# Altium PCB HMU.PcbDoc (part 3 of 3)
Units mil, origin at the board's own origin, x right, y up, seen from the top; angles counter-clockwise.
Board outline 6247.81 x 4035.43 mil, 4 copper layers (Top Layer, Mid-Layer 1, Mid-Layer 2, Bottom Layer), stack 90 mil thick; 310 components, 201 nets, 779 pads, 176 vias.
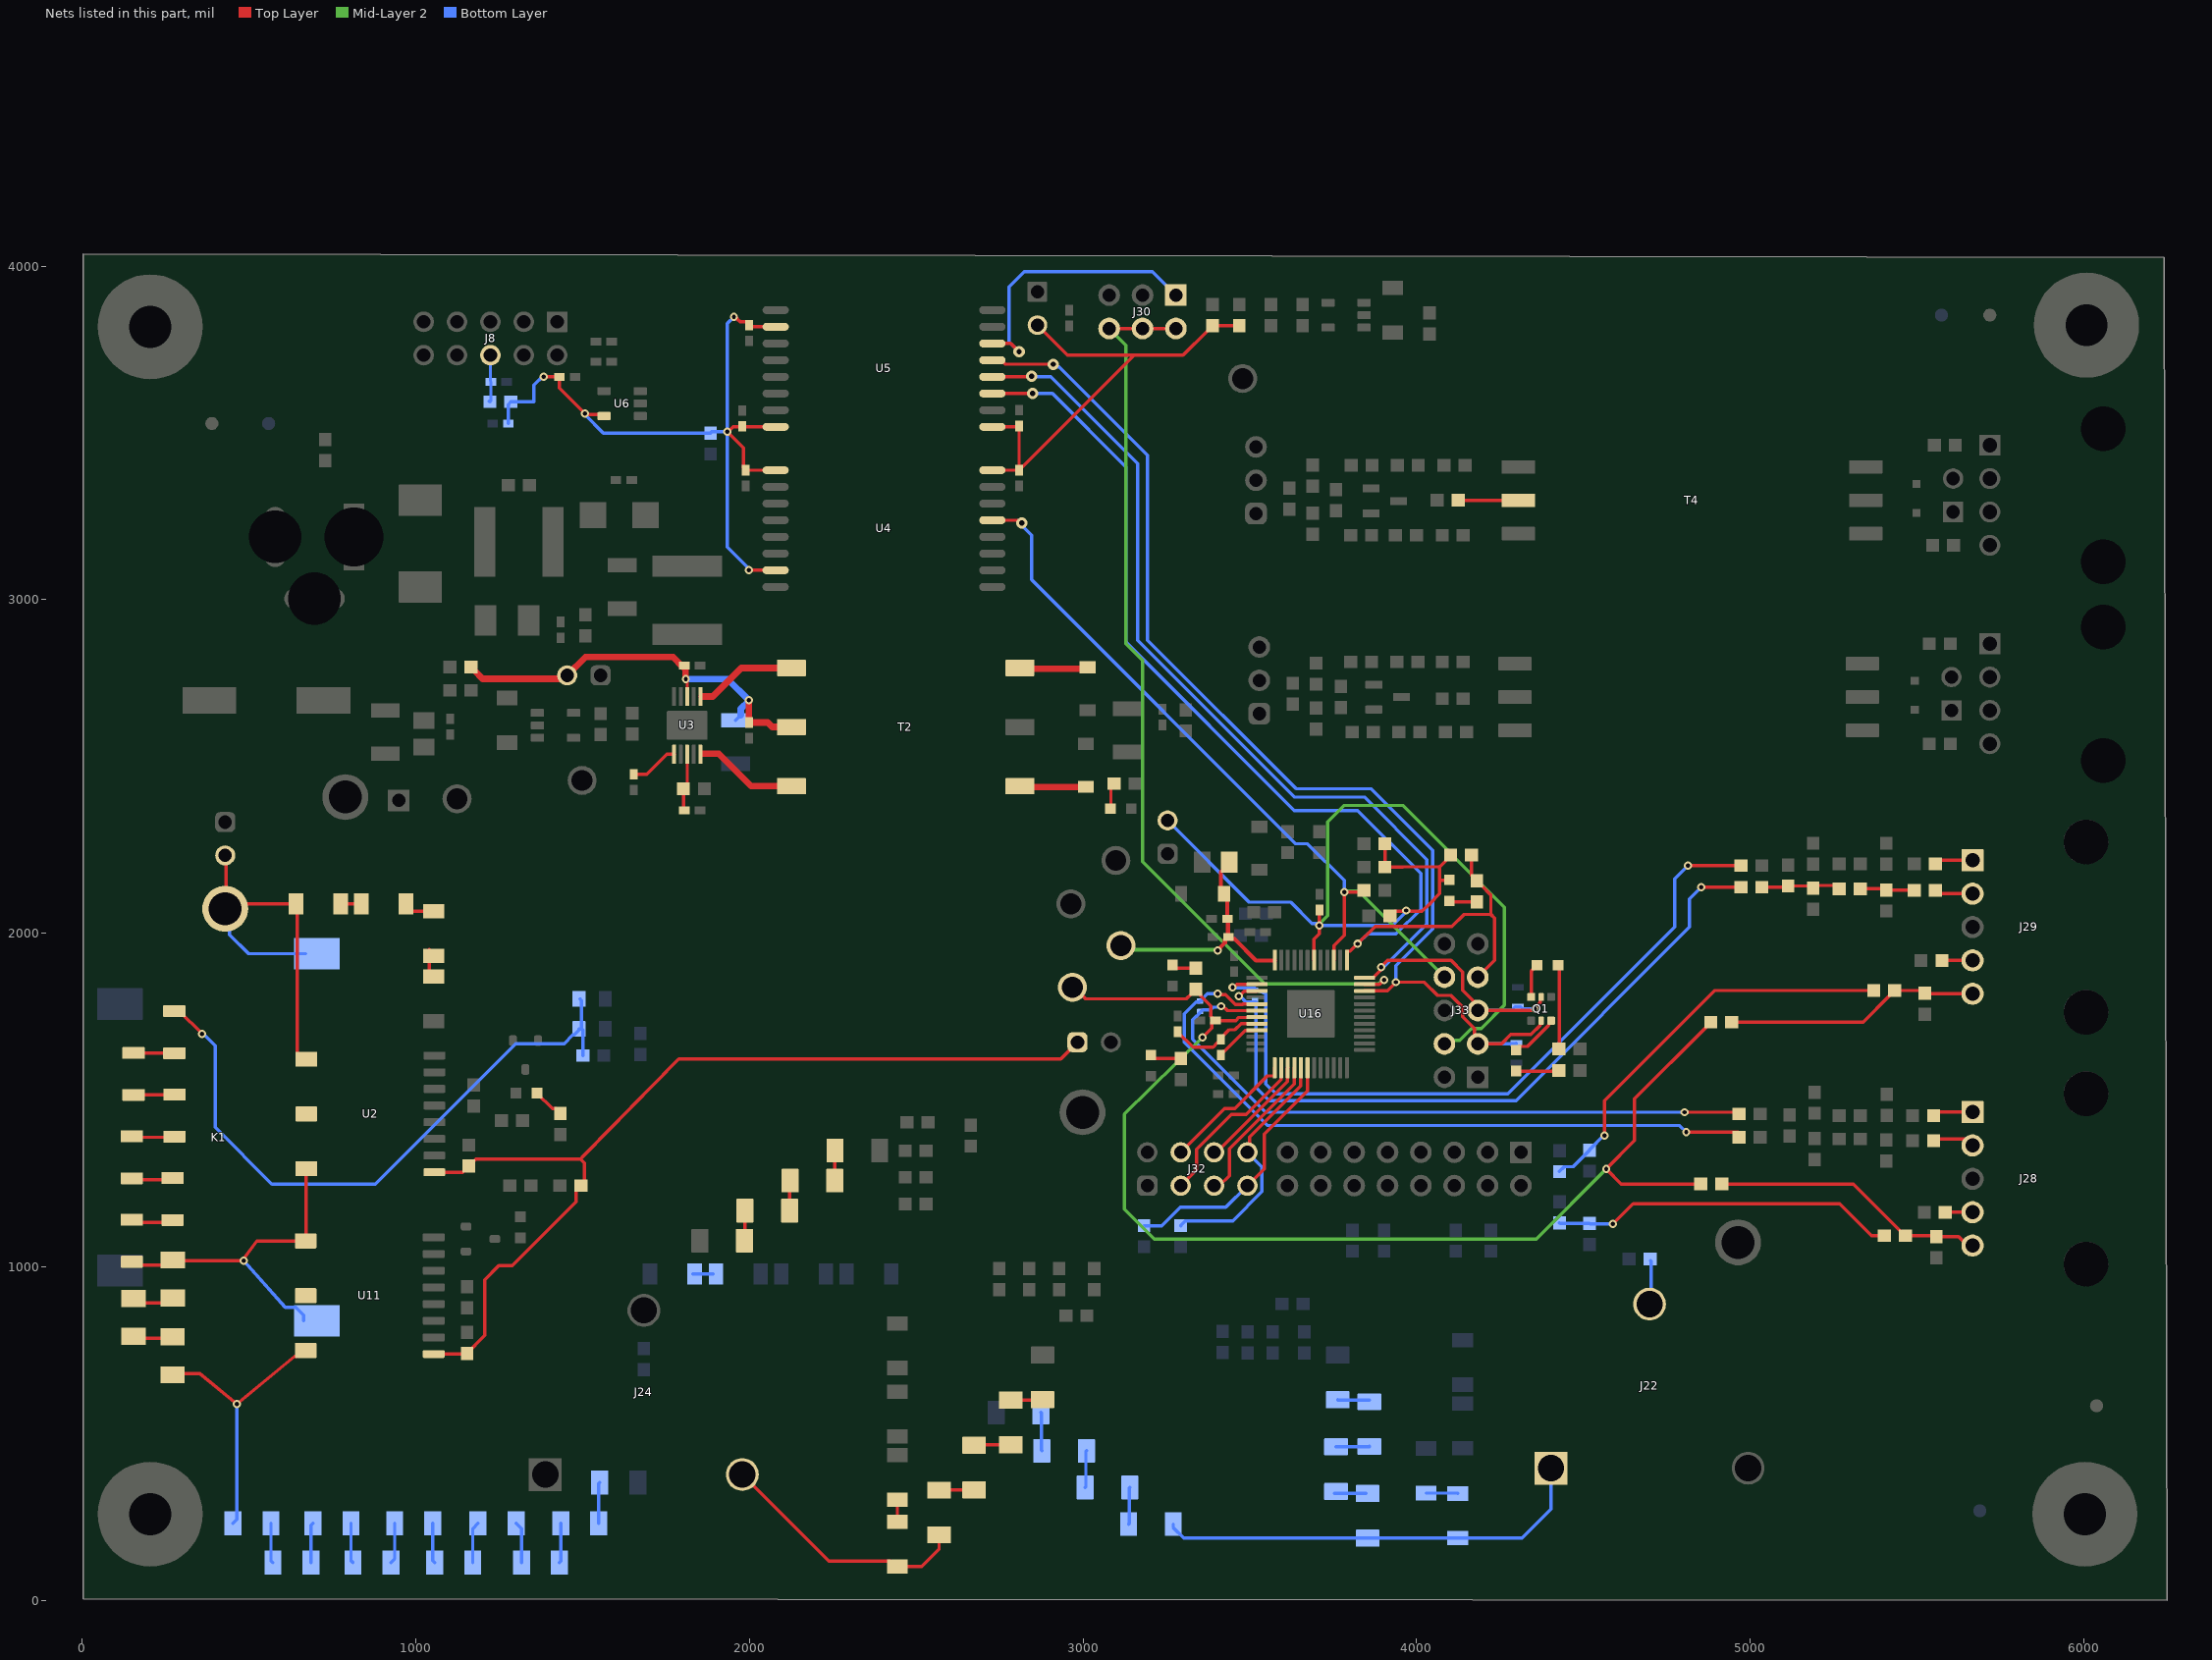
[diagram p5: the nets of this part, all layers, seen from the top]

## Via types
v1: diameter 24.8, hole 12.99, Top Layer to Bottom Layer, 142 vias
v2: diameter 50, hole 28, Top Layer to Bottom Layer, 19 vias
v3: diameter 34, hole 16, Top Layer to Bottom Layer, 9 vias
v4: diameter 19.68, hole 7.87, Top Layer to Bottom Layer, 6 vias

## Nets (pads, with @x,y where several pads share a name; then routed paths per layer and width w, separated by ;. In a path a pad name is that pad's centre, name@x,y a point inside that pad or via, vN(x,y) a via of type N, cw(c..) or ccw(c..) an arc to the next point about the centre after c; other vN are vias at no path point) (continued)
NetC78_2: C78.2 C80.1 R209.1 R210.2 | length 244
  Top Layer w10: R209.1@5034.76,2137.8 5109.7,2137.8 C78.2@5113.2,2141.3 5181.26,2141.3 C80.1@5188.27,2134.29 5196.77,2142.8 5256.77,2142.8 R210.2@5266.77,2132.8
NetC81_1: C81.1 R210.1 R211.1 | length 166.2
  Top Layer w10: R210.1@5329.76,2132.8 5404.76,2132.8 C81.1@5408.27,2129.29 5490.28,2129.29 R211.1@5491.77,2127.8 R211.1@5490.28,2126.3
NetC105_1: C105.1 T4.5 | length 171.7
  Top Layer w10: C105.1@4133.27,3297.8 T4.5@4304.96,3297.8
NetC108_HV1_1: C108_HV1.1 C500_HV1.2 | length 61.1
  Bottom Layer w10: C500_HV1.2@1830.2,977.8 C108_HV1.1@1891.34,977.8
NetC108_HV3_1: C108_HV3.1 C500_HV3.2 | length 66.1
  Top Layer w10: C500_HV3.2@2443.27,219.72 C108_HV3.1@2443.27,285.87
NetC108_HV4_1: C108_HV4.1 C500_HV4.2 | length 95.5
  Bottom Layer w10: C108_HV4.1@4028.27,320.87 4122.13,320.87 C500_HV4.2@4123.27,319.72
NetC112_1: C112.1 C114.2 | length 86.7
  Top Layer w10: C114.2@1040.2,1951.03 1040.2,1882.8 C112.1@1053.27,1869.72
NetC113_1: C113.1 C115.2 | length 62.2
  Top Layer w10: C115.2@774.12,2087.8 C113.1@836.34,2087.8
NetC113_2: C113.2 C114.1 | length 95.3
  Top Layer w10: C113.2@970.2,2087.8 970.2,2082.45 986.85,2065.8 C114.1@1053.27,2065.8
NetD2_2: D2.2 R38.1 | length 96.1
  Top Layer w10: D2.2@1362.87,1520 1408.9,1473.98 1419.57,1473.98 1433.27,1460.28 R38.1@1433.27,1459.29
NetD30_2: D30.2 R310.1 | length 60
  Top Layer w10: D30.2@3083.27,2383.76 R310.1@3083.27,2443.76
NetD31_2: D31.2 R311.1 | length 74.1
  Top Layer w10: D31.2@3268.27,1904.29 3278.27,1894.29 R311.1@3338.27,1894.29
NetD32_2: D32.2 R312.1 | length 94.1
  Top Layer w10: D32.2@3203.27,1634.29 3213.27,1624.29 R312.1@3293.27,1624.29
NetD33_1: D33.1 Q1.6 | length 145.2
  Top Layer w10: D33.1@4298.27,1649.29 4309.02,1660.04 4332.68,1660.04 4395.98,1723.34 4395.98,1730.55 Q1.6@4402.8,1737.36
NetD33_2: D33.2 R42.1 | length 129.1
  Top Layer w10: D33.2@4298.27,1586.3 4425.28,1586.3 R42.1@4426.77,1587.8
NetD34_1: D34.1 Q1.3 | length 103
  Top Layer w10: Q1.3@4343.74,1808.23 4343.74,1886.74 D34.1@4361.02,1904.03
NetD34_2: D34.2 R41.1 | length 253
  Top Layer w10: D34.2@4424.02,1904.03 4427.48,1900.56 4427.48,1824.2 4427.48,1653.5 R41.1@4426.77,1652.8
NetD301_1: D301.1 R503.2 | length 83.4
  Top Layer w10: D301.1@4098.07,2096.3 4100.99,2093.38 R503.2@4180.28,2093.38
NetJ22_2: J22.2 R405.1 | length 129.6
  Bottom Layer w10: R405.1@4701.77,1017.8 4703.27,1016.3 J22.2@4703.27,888.86
NetK1_4: K1.4 R27.2 R28.2 U2.11 U11.9 | length 1034.9
  Top Layer w10: R28.2@148.61,1004.8 270.94,1004.8 R27.2@271.02,1004.88 ; R27.2@270.93,1019.88 273.02,1017.8 v1(483.27,1017.8) ; v1@483.27,1022.8 523.27,1076.97 U11.9@669.41,1076.97 ; U11.9@670.37,1076.97 670.37,1292.66 U2.11@671.34,1293.62
  Bottom Layer w10: v1(483.27,1017.8) 608.27,877.8 639.37,877.8 663.27,853.9 K1.4@663.27,837.8
NetR5_1: R5.1 R6.2 | length 124
  Bottom Layer w10: R6.2@1548.27,230.04 1548.27,247.8 1548.27,349.88 R5.1@1551.18,352.8
NetR6_1: R6.1 R7.2 | length 118.8
  Bottom Layer w10: R7.2@1430.35,112.8 1434.09,116.54 R6.1@1434.09,230.04
NetR7_1: R7.1 R8.2 | length 123.8
  Bottom Layer w10: R8.2@1300.35,230.04 1316.18,214.21 R7.1@1316.18,112.8
NetR8_1: R8.1 R9.2 | length 123.8
  Bottom Layer w10: R9.2@1170.35,112.8 1170.35,214.21 R8.1@1186.18,230.04
NetR9_1: R9.1 R10.2 | length 119.7
  Bottom Layer w10: R10.2@1050.35,230.04 1050.35,118.62 R9.1@1056.18,112.8
NetR10_1: R10.1 R11.2 | length 121.7
  Bottom Layer w10: R11.2@925.35,112.8 936.18,123.62 R10.1@936.18,230.04
NetR11_1: R11.1 R13.2 | length 119.7
  Bottom Layer w10: R13.2@805.35,230.04 805.35,118.62 R11.1@811.18,112.8
NetR13_1: R13.1 R17.2 | length 119.7
  Bottom Layer w10: R17.2@685.35,112.8 685.35,224.21 R13.1@691.18,230.04
NetR17_1: R17.1 R18.2 | length 119.7
  Bottom Layer w10: R18.2@565.35,230.04 565.35,118.62 R17.1@571.18,112.8
NetR18_1: R18.1 R19.1 U11.11 | length 853.4
  Top Layer w10: R19.1@270.51,679.76 351.3,679.76 v1(463.27,587.8) 636.28,730.81 641.75,730.81 659.57,748.62 U11.11@669.41,748.62
  Bottom Layer w10: R18.1@451.18,230.04 463.27,242.13 v1(463.27,587.8)
NetR19_2: R19.2 R20.1 | length 121.2
  Top Layer w10: R20.1@153.27,785.71 262.8,785.71 R19.2@271.02,793.93
NetR20_2: R20.2 R27.1 | length 121.6
  Top Layer w10: R20.2@153.27,899.88 162.44,890.71 R27.1@271.02,890.71
NetR28_1: R28.1 R29.2 | length 124.7
  Top Layer w10: R28.1@148.61,1130.79 150.61,1132.8 268.97,1132.8 270.98,1134.8 R29.2@271.47,1135.3
NetR29_1: R29.1 R30.2 | length 123.8
  Top Layer w10: R30.2@148.27,1259.8 148.76,1260.3 270.49,1260.3 270.98,1260.79 R29.1@271.47,1260.3
NetR30_1: R30.1 R32.2 | length 132.1
  Top Layer w10: R30.1@148.27,1385.79 150.28,1387.8 273.89,1387.8 R32.2@275.9,1389.8 R32.2@277.9,1387.8
NetR32_1: R32.1 R33.2 | length 123.7
  Top Layer w10: R33.2@153.27,1514.8 153.76,1515.3 275.4,1515.3 R32.1@275.9,1515.79 R32.1@276.39,1515.3
NetR33_1: R33.1 R35.2 | length 122.8
  Top Layer w10: R33.1@153.27,1640.79 153.76,1640.3 275.15,1640.3 R35.2@275.64,1639.8
NetR35_1: R35.1 R36.2 R37.2 R66.2 | length 1939.9
  Top Layer w10: R35.1@275.64,1765.79 291.39,1765.79 358.27,1698.91 v1(358.27,1697.8)
  Bottom Layer w10: v1(358.27,1697.8) 362.27,1697.8 376.03,1684.04 376.2,1684.04 398.27,1661.97 398.27,1417.8 568.27,1247.8 878.27,1247.8 1298.54,1668.07 1444.17,1668.07 1470.28,1694.17 1474.21,1694.17 1488.9,1708.86 R36.2@1488.9,1712.8 ; R37.2@1491.77,1802.8 1496.77,1797.8 1496.77,1712.8 1500.28,1709.29 R66.2@1500.28,1632.8
NetR265_HV1_1: R265_HV1.1 R266_HV1.2 | length 90.5
  Top Layer w10: R265_HV1.1@1985.2,1077.8 1985.77,1078.37 1985.77,1167.22 R266_HV1.2@1986.34,1167.8
NetR265_HV3_1: R265_HV3.1 R266_HV3.2 | length 110.5
  Top Layer w10: R265_HV3.1@2563.27,329.72 2563.84,330.3 2672.7,330.3 R266_HV3.2@2673.27,330.87
NetR265_HV4_1: R265_HV4.1 R266_HV4.2 | length 95.5
  Bottom Layer w10: R266_HV4.2@3753.27,320.87 3753.84,320.3 3847.7,320.3 R265_HV4.1@3848.27,319.72
NetR266_HV1_1: R266_HV1.1 R267_HV1.2 | length 90.5
  Top Layer w10: R266_HV1.1@2120.2,1167.8 2120.77,1168.37 2120.77,1257.22 R267_HV1.2@2121.34,1257.8
NetR266_HV3_1: R266_HV3.1 R267_HV3.2 | length 110.5
  Top Layer w10: R266_HV3.1@2673.27,464.72 2673.84,465.3 2782.7,465.3 R267_HV3.2@2783.27,465.87
NetR266_HV4_1: R266_HV4.1 R267_HV4.2 | length 101.3
  Bottom Layer w10: R266_HV4.1@3758.27,459.72 3758.84,460.3 3857.7,460.3 R267_HV4.2@3858.27,460.87 R267_HV4.2@3858.84,460.3
NetR267_HV1_1: R267_HV1.1 R272_HV1.2 | length 90.5
  Top Layer w10: R267_HV1.1@2255.2,1257.8 2255.77,1258.37 2255.77,1347.22 R272_HV1.2@2256.34,1347.8
NetR267_HV3_1: R267_HV3.1 R272_HV3.2 | length 95.5
  Top Layer w10: R267_HV3.1@2783.27,599.72 2783.84,600.3 2877.7,600.3 R272_HV3.2@2878.27,600.87
NetR267_HV4_1: R267_HV4.1 R272_HV4.2 | length 95.5
  Bottom Layer w10: R272_HV4.2@3763.27,600.87 3763.84,600.3 3857.7,600.3 R267_HV4.1@3858.27,599.72
NetR300_1: R300.1 R301.2 | length 116.3
  Bottom Layer w10: R300.1@2873.27,562.8 2874.8,561.26 2874.8,449.33 R301.2@2876.34,447.8
NetR301_1: R301.1 R302.2 | length 111.6
  Bottom Layer w10: R302.2@3006.34,337.8 3008.27,339.72 3008.27,445.87 R301.1@3010.2,447.8
NetR302_1: R302.1 R303.2 | length 111.6
  Bottom Layer w10: R303.2@3136.34,227.8 3138.27,229.72 3138.27,335.87 R302.1@3140.2,337.8
nFAULT: J33.7 R40.2 R503.1 U5.3 U16.25 | length 3446.2
  Top Layer w10: U5.3@2728.07,3617.8 v3(2848.27,3617.8) ; U16.25@3790.91,1919.21 3790.91,1944.8 3791.81,1945.71 3801.18,1945.71 v1(3823.27,1967.8) 3875.26,2019.78 4105.77,2019.78 4141.93,2055.94 4222.52,2055.94 ; R40.2@4164.76,2234.03 4164.76,2172.87 4180.28,2157.36 4180.28,2155.39 4193.98,2141.69 4194.96,2141.69 4222.52,2114.13 4222.52,2055.94 ; J33.7@4183.27,1867.8 4233.27,1917.8 4233.27,2045.2 4222.52,2055.94
  Bottom Layer w10: v3(2848.27,3617.8) 2908.27,3617.8 3128.27,3397.8 3128.27,2872.8 3633.27,2367.8 3823.27,2367.8 4012.52,2178.54 4012.52,2072.05 3938.27,1997.8 3853.27,1997.8 v1(3823.27,1967.8)
NTC1: C82.1 R117.2 R213.1 | length 1039.9
  Top Layer w10: v1(4588.27,1127.8) 4649.14,1188.67 5268.27,1188.67 5364.14,1092.8 R213.1@5401.77,1092.8
  Bottom Layer w10: R117.2@4428.27,1131.3 4430.28,1129.29 C82.1@4518.27,1129.29 4519.76,1127.8 v1(4588.27,1127.8)
NTC1_RTN: J28.4 R214.2 | length 81.7
  Top Layer w10: R214.2@5584.76,1162.8 5585.16,1163.19 J28.4@5666.34,1163.19
NTC1_SNS: C83.1 J28.5 R212.1 R213.2 | length 833.8
  Top Layer w10: R212.1@4908.97,1247.8 R212.1@4914.76,1247.8 5308.78,1247.8 5463.78,1092.8 R213.2@5464.76,1092.8 5554.76,1092.8 C83.1@5558.27,1089.29 5624.94,1089.29 5651.04,1063.19 J28.5@5666.34,1063.19
NTC2: C84.1 R122.2 R218.1 | length 1240.4
  Top Layer w10: v1(4563.27,1392.8) 4563.27,1497.8 4893.27,1827.8 R218.1@5380.54,1827.8
  Bottom Layer w10: R122.2@4428.27,1284.8 4428.27,1285.79 4441.97,1299.49 4469.45,1299.49 4518.27,1348.31 4518.27,1350.28 4560.79,1392.8 v1(4563.27,1392.8)
NTC2_RTN: J29.4 R219.2 | length 91.7
  Top Layer w10: R219.2@5574.76,1917.8 5575.16,1918.19 J29.4@5666.34,1918.19
NTC2_SNS: C85.1 J29.5 R216.1 R218.2 | length 765.5
  Top Layer w10: R216.1@4944.76,1732.8 5338.27,1732.8 5418.58,1813.11 5418.58,1814.09 5432.28,1827.8 5514.76,1827.8 C85.1@5523.27,1819.29 5524.37,1818.19 J29.5@5666.34,1818.19
nUART/SPI: J30.1 U5.6 | length 845.6
  Top Layer w10: U5.6@2728.07,3767.8 2783.27,3767.8 v3(2808.27,3742.8)
  Bottom Layer w10: v3(2808.27,3742.8) 2778.27,3772.8 2778.27,3937.8 2823.27,3982.8 3208.27,3982.8 J30.1@3278.27,3912.8
OC1: J33.5 Q1.2 R3.2 U5.4 U16.24 | length 3452.6
  Top Layer w10: U5.4@2728.07,3667.8 2728.79,3668.51 2844.75,3668.51 v3(2845.47,3669.23) ; U16.24@3844.06,1866.06 3844.96,1866.97 3870.55,1866.97 v1@3890.44,1886.85 ; v1@3890.44,1895.44 3912.8,1917.8 4103.27,1917.8 4137.91,1883.15 4137.91,1828.15 4167.19,1798.87 4167.19,1798.74 4183.27,1782.67 J33.5@4183.27,1767.8 4346,1767.8 4351,1772.8 v1(4355.01,1772.8) 4355.01,1776.8 4370.39,1792.19 4370.39,1805.35 Q1.2@4373.27,1808.23
  Bottom Layer w10: v3(2845.47,3669.23) 2846.83,3669.23 2848.27,3667.8 2903.27,3667.8 3163.27,3407.8 3163.27,2877.8 3633.27,2407.8 3843.27,2407.8 4030.39,2220.67 4030.39,2027.52 3901.14,1898.27 v1(3893.27,1898.27) ; J33.5@4183.27,1767.8 4284.92,1767.8 4295.39,1778.27 4311.14,1778.27 4315.98,1773.43 4321.21,1773.43 4321.84,1772.8 v1(4355.01,1772.8)
OC2: J33.3 Q1.5 R4.2 U5.5 U16.22 | length 3502.2
  Top Layer w10: U5.5@2728.07,3717.8 2756.1,3717.8 2768.3,3705.6 v3(2910.54,3705.6) ; U16.22@3844.06,1826.69 3912.17,1826.69 v1(3938.27,1852.8) 4023.27,1852.8 4062.91,1813.15 4102.05,1813.15 4137.4,1777.8 4137.4,1749.52 4172.75,1714.17 4172.75,1678.31 J33.3@4183.27,1667.8 4254.83,1667.8 4282.61,1695.58 4342.61,1695.58 4370.39,1723.36 4370.39,1734.49 Q1.5@4373.27,1737.36
  Bottom Layer w10: v3(2910.54,3705.6) 2911.07,3705.6 2913.27,3707.8 2923.27,3697.8 2928.27,3697.8 3193.27,3432.8 3193.27,2877.8 3638.27,2432.8 3863.27,2432.8 4048.27,2247.8 4048.27,2012.8 3938.27,1902.8 v1(3938.27,1852.8) ; J33.3@4183.27,1667.8 4184.17,1668.7 4297.68,1668.7 R4.2@4298.58,1669.61
PE: C115.1 J10.2 K1.3 TP10.1 U2.9 | length 1207
  Top Layer w10: TP10.1@428.27,2072.8 TP10.1@430.77,2075.3 ; J10.2@428.27,2232.8 430.77,2230.3 TP10.1@430.77,2075.3 ; U2.9@663.27,1630.04 U2.9@671.34,1621.97 661.5,1621.97 643.86,1639.61 643.86,2084.2 C115.1@640.27,2087.8 443.27,2087.8 TP10.1@430.77,2075.3
  Bottom Layer w10: TP10.1@428.27,2072.8 441.31,2059.76 441.31,1994.76 497.87,1938.19 K1.3@668.82,1938.19
PWR_6507: C21.1 C22.1 C23.1 J5.2 R12.2 T2.2 U3.3 | length 1279
  Top Layer w10: C23.1@1800.71,2797.8 C23.1@1804.65,2797.8 ; v1(1809,2761.56) 1809,2757.56 1813.27,2753.29 U3.3@1813.27,2709.41
  Top Layer w20: R12.2@1164.76,2797.8 1165.75,2797.8 1174.45,2789.09 1174.45,2788.11 1199.76,2762.8 1432.38,2762.8 1442.38,2772.8 J5.2@1453.27,2772.8 1508.27,2827.8 1770.71,2827.8 C23.1@1800.71,2797.8 ; C23.1@1804.65,2797.8 1806.27,2797.8 1808.08,2795.98 1808.08,2762.48 v1(1809,2761.56) ; v1(1998.27,2697.8) C22.1@1998.27,2631.42 2054.65,2631.42 2068.27,2617.8 T2.2@2125.75,2617.8
  Bottom Layer w10: C21.1@1958.27,2637.76 C21.1@1974.02,2653.51
  Bottom Layer w20: v1(1809,2761.56) 1934.5,2761.56 v1(1998.27,2697.8) 1998.27,2696.5 1974.02,2672.25 C21.1@1974.02,2653.51
RACKN: C500_HV4.1 J22.1 R265_HV4.2 R303.1 | length 1315
  Bottom Layer w10: R303.1@3270.2,227.8 3270.2,217.95 3302.28,185.87 R265_HV4.2@3853.27,185.87 C500_HV4.1@4123.27,185.87 4316.34,185.87 4402.99,272.52 J22.1@4402.99,395.67
RACKP: C500_HV3.1 J24.3 R265_HV3.2 | length 767.8
  Top Layer w10: J24.3@1978.54,376.73 2237.76,117.52 2421.46,117.52 C500_HV3.1@2441.18,97.8 ; C500_HV3.1@2443.27,100.87 2516.34,100.87 2568.27,152.8 R265_HV3.2@2568.27,195.87
REF_CAP: C94.1 U16.45 | length 141.1
  Top Layer w10: C94.1@3413.27,1634.17 3413.27,1638.11 3420.08,1644.92 3422.78,1644.92 3485.53,1707.68 3520.32,1707.68 U16.45@3521.22,1708.58
REF_VSS: C94.2 R221.1 U16.44 | length 291
  Top Layer w10: R221.1@3283.27,1704.17 3329.65,1657.8 3389.65,1657.8 3402.52,1670.67 3406.46,1670.67 3413.27,1677.48 3413.27,1685.35 3438.13,1710.22 3455.69,1710.22 3473.74,1728.27 U16.44@3521.22,1728.27
SCLK: J33.8 R504.1 U4.13 U16.27 | length 2305.2
  Top Layer w10: U4.13@2727.87,3237.8 2801.8,3237.8 2810.19,3229.4 v3(2816.69,3229.4) ; U16.27@3751.54,1919.21 3752.44,1920.12 3752.44,1962.25 3783.27,1993.07 3783.27,2037.05 3782.99,2037.33 3782.99,2058.26 3783.27,2058.54 v1(3783.27,2122.8) 3836.77,2122.8 R504.1@3841.77,2127.8
  Mid-Layer 2 w10: v1(3783.27,2122.8) 3785.87,2125.39 3825.67,2125.39 J33.8@4083.27,1867.8
  Bottom Layer w10: v3(2816.69,3229.4) 2816.69,3222.91 2846.14,3193.45 2846.14,3059.64 3637.99,2267.8 3673.27,2267.8 3783.27,2157.8 v1(3783.27,2122.8)
SM1: U11.10
SM2: U2.10
SO1: D6.2 T2.6 | length 180
  Top Layer w20: T2.6@2823.27,2792.8 D6.2@3003.27,2792.8
SO2: D7.2 T2.4 | length 163.4
  Top Layer w10: D7.2@3005.96,2440.63 D7.2@3008.27,2438.33
  Top Layer w20: T2.4@2828.27,2437.8 D7.2@2988.44,2437.8
SR_6507: R16.2 U3.6 | length 145.4
  Top Layer w10: R16.2@1653.27,2476.42 1691.89,2476.42 1751.65,2536.18 U3.6@1773.9,2536.18
SRN1: C73.2 R199.2 U16.41 | length 2124.4
  Top Layer w10: v1(3403.27,1817.8) 3406.1,1814.96 3427.13,1814.96 3456.74,1785.35 3477.68,1785.35 3478.33,1786 ; 3478.33,1787.32 U16.41@3521.22,1787.32 ; v1(4808.27,1402.8) R199.2@4963.27,1402.8 ; R199.2@4965.77,1397.8 4963.27,1397.8 R199.2@4968.27,1392.8
  Bottom Layer w10: v1(3403.27,1817.8) 3372.31,1817.8 3355.8,1801.28 3355.8,1799.32 3352.93,1796.44 C73.2@3350.96,1796.44 3348.08,1793.57 3338.45,1793.57 3303.27,1758.38 3303.27,1672.8 3552.99,1423.07 4787.99,1423.07 v1(4808.27,1402.8)
SRN1_RES: J28.2 R201.2 | length 128.8
  Top Layer w10: R201.2@5549.76,1382.8 J28.2@5663.27,1382.8 ; J28.2@5651.04,1363.19 J28.2@5666.34,1363.19
SRN2: C79.2 R209.2 U16.39 | length 2163.8
  Top Layer w10: v1(3467.21,1810.62) 3468.18,1810.62 3483.34,1825.79 3520.32,1825.79 U16.39@3521.22,1826.69 ; v1(4853.27,2137.8) R209.2@4971.77,2137.8
  Bottom Layer w10: v1@3464.38,1813.46 v1(3467.21,1810.62) 3471.22,1810.62 3487.89,1793.95 3518.27,1793.95 3518.27,1537.8 3558.27,1497.8 4298.27,1497.8 4818.27,2017.8 4818.27,2102.8 v1(4853.27,2137.8)
SRN2_RES: J29.2 R211.2 | length 115.6
  Top Layer w10: R211.2@5554.76,2127.8 5564.37,2118.19 J29.2@5666.34,2118.19
SRP1: C73.1 R196.2 U16.42 | length 1996.4
  Top Layer w10: v1@3413.75,1782.17 3417.76,1782.17 3432.45,1767.48 3521.06,1767.48 U16.42@3521.22,1767.64 ; v1(4803.27,1462.8) R196.2@4958.27,1462.8
  Bottom Layer w10: C73.1@3348.27,1759.48 3356.51,1767.72 3357.35,1767.72 3358.99,1769.37 3381.35,1769.37 3389.85,1777.86 3410.92,1777.86 v1(3413.75,1780.69) ; C73.1@3348.27,1760.96 3348.27,1759.27 3340.03,1751.03 3339.19,1751.03 3328.27,1740.11 3328.27,1682.05 3547.52,1462.8 v1(4803.27,1462.8)
SRP1_RES: J28.1 R198.2 | length 118.8
  Top Layer w10: R198.2@5549.76,1452.8 R198.2@5555.16,1458.19 ; R198.2@5555.16,1463.19 J28.1@5666.34,1463.19
SRP2: C79.1 R206.2 U16.38 | length 2257.1
  Top Layer w10: v1(3448.27,1837.8) 3452.27,1837.8 3460.86,1846.38 U16.38@3521.22,1846.38 ; v1(4813.27,2202.8) R206.2@4971.77,2202.8
  Bottom Layer w10: v1(3448.27,1837.8) 3450.16,1835.9 3514,1835.9 3522.11,1827.8 3548.27,1817.8 3548.27,1547.8 3578.27,1517.8 4273.27,1517.8 4773.27,2017.8 4773.27,2162.8 v1(4813.27,2202.8)
SRP2_RES: J29.1 R208.2 | length 115.9
  Top Layer w10: R208.2@5554.76,2207.8 5565.16,2218.19 J29.1@5666.34,2218.19
SS_6507: C26.1 R15.2 U3.8 | length 174.3
  Top Layer w10: R15.2@1804.65,2367.8 1801.77,2370.67 C26.1@1801.77,2432.8 1813.27,2444.29 U3.8@1813.27,2536.18
SW1: J32.5 U16.4 | length 462.5
  Top Layer w10: J32.5@3392.64,1242.8 3408.27,1242.8 3438.27,1272.8 3438.27,1352.8 3632.9,1547.42 3632.9,1595.85 U16.4@3633.43,1596.38
SW1_6507: T2.1 U3.1 | length 303.9
  Top Layer w20: U3.1@1857.29,2709.41 1889.88,2709.41 1975.43,2794.96 T2.1@2125.75,2794.96
SW2: J32.6 U16.3 | length 349.8
  Top Layer w10: J32.6@3392.64,1342.8 3400.53,1342.8 3612.83,1555.1 3612.83,1595.47 U16.3@3613.74,1596.38
SW2_6507: T2.3 U3.10 | length 307.7
  Top Layer w20: U3.10@1858.27,2537.8 1908.27,2537.8 2005.43,2440.63 T2.3@2125.75,2440.63
SW3: J32.3 U16.2 | length 504.2
  Top Layer w10: J32.3@3292.64,1242.8 3340.51,1290.67 3340.51,1352.02 3444.84,1456.36 3488.82,1456.36 3593.15,1560.69 3593.15,1595.47 U16.2@3594.06,1596.38
SW4: J32.4 U16.1 | length 400.6
  Top Layer w10: J32.4@3292.64,1342.8 3424.07,1474.23 3454.84,1474.23 3552.44,1571.83 3573.46,1571.83 3574.37,1572.74 U16.1@3574.37,1596.38
SW_5V: C14.1 C49.1 J11.1 R350.1 U2.1 U11.1 | length 2944.9
  Top Layer w10: U11.1@1053.27,737.8 1151.26,737.8 1151.26,738.78 1206.14,793.66 1206.14,960.67 1248.27,1002.8 1288.27,1002.8 1480.08,1194.61 1480.08,1229.09 1493.78,1242.8 R350.1@1494.76,1242.8 1505.47,1253.51 1505.47,1310.43 1493.11,1322.8 ; U2.1@1060.2,1282.8 1139.76,1282.8 C14.1@1158.27,1301.3 1179.76,1322.8 1493.11,1322.8 ; J11.1@2983.27,1672.8 2933.27,1622.8 1788.27,1622.8 1502.95,1332.8 1493.11,1322.8
TSREF: C95.1 R212.2 R216.2 R311.2 TP7.1 U16.43 | length 3774.4
  Top Layer w10: TP7.1@2968.27,1837.8 2972.71,1837.8 3007.71,1802.8 3309.76,1802.8 3323.58,1816.61 3324.57,1816.61 3338.27,1830.31 R311.2@3338.27,1831.3 3351.97,1817.6 3351.97,1812.6 3383.27,1781.31 3383.27,1750.46 3386.14,1747.59 3386.14,1744.61 3389.76,1740.98 3396.14,1740.98 3386.14,1730.98 3386.14,1715.67 v1(3358.27,1687.8) ; C95.1@3396.89,1737.8 3457.99,1737.8 3467.24,1747.05 3491.13,1747.05 3520.32,1747.05 U16.43@3521.22,1747.95 ; R212.2@4857.68,1247.8 R212.2@4851.77,1247.8 4613.27,1247.8 v1(4568.27,1292.8) 4653.27,1377.8 4653.27,1502.8 4867.09,1716.61 4867.09,1719.09 4881.03,1733.04 R216.2@4883.51,1733.04
  Mid-Layer 2 w10: v1(3358.27,1687.8) 3124.32,1457.16 3124.32,1171.74 3213.27,1082.8 4358.27,1082.8 v1(4568.27,1292.8)
U\/S: J30.2 J30.4 J30.6 U16.23 | length 2784.1
  Top Layer w10: J30.6@3078.27,3812.8 J30.4@3178.27,3812.8 J30.2@3278.27,3812.8 ; U16.23@3844.06,1846.38 3888.4,1846.38 v1(3901.86,1859.84)
  Mid-Layer 2 w10: J30.6@3078.27,3812.8 3128.27,3762.8 3128.27,3758.65 3128.27,2867.8 3178.27,2817.8 3178.27,2213.98 3544.73,1847.52 3885.54,1847.52 3897.85,1859.84 v1(3901.86,1859.84)
USB2ANY_3.3V: C151.2 J8.6 R403.1 | length 140.6
  Bottom Layer w10: R403.1@1219.65,3594.92 R403.1@1221.77,3592.8 1224.65,3595.67 C151.2@1224.65,3652.8 ; C151.2@1223.27,3656.42 J8.6@1223.27,3732.8
VCC_DISO: C29.1 C30.1 C31.1 R21.2 R24.2 R26.2 R403.2 U4.1 U4.7 U5.10 U5.16 U6.5 | length 2313.5
  Top Layer w10: v1(1383.27,3667.8) R21.2@1429.65,3667.8 1429.65,3633.9 v1(1506.34,3557.2) 1509.18,3554.37 1560.16,3554.37 U6.5@1564.13,3550.39 ; v1(1953.27,3847.8) 1971.53,3833.54 1991.46,3833.54 1998.27,3826.73 R24.2@1998.27,3822.8 2003.27,3817.8 U5.10@2078.46,3817.8 ; v1@1958.27,3842.8 v1@1962.27,3842.8 ; v1@2005.89,3087.8 U4.7@2078.27,3087.8 ; U4.1@2078.27,3387.8 C31.1@1988.27,3387.8 1981.46,3394.61 1981.46,3454.61 v1(1933.27,3502.8) 1936.46,3502.8 1951.46,3517.8 U5.16@2078.46,3517.8
  Bottom Layer w10: C29.1@1276.89,3527.8 1276.89,3584.92 R403.2@1284.76,3592.8 1353.27,3592.8 1353.27,3642.8 v1@1380.77,3670.3 ; v1(1506.34,3557.2) 1506.34,3554.72 1561.77,3499.29 R26.2@1883.27,3499.29 1886.77,3502.8 v1(1933.27,3502.8) ; v1(1953.27,3847.8) 1933.27,3827.8 v1(1933.27,3502.8) ; v1@1998.27,3092.8 1933.27,3157.8 v1(1933.27,3502.8)
  other v1: 1998.27,3087.8
VDD_DISO: C27.1 C28.1 J9.2 R402.2 R404.2 U4.16 U5.1 | length 1464.2
  Top Layer w10: U4.16@2727.87,3387.8 C28.1@2808.27,3387.8 ; U5.1@2728.07,3517.8 2805.51,3517.8 C27.1@2808.27,3520.55 C28.1@2808.27,3387.8 ; J9.2@2863.27,3822.8 2953.27,3732.8 3153.27,3732.8 ; R404.2@3468.27,3821.3 R402.2@3388.27,3821.3 3388.27,3820.31 3374.57,3806.61 3373.58,3806.61 3299.76,3732.8 3153.27,3732.8 ; C28.1@2808.27,3387.8 2808.27,3391.73 2815.08,3398.54 2819.02,3398.54 3153.27,3732.8
VF1: J32.8 R108.1 U16.5 | length 742.2
  Top Layer w10: J32.8@3492.64,1342.8 3499.33,1349.49 3499.33,1388.31 3652.58,1541.55 3652.58,1595.85 U16.5@3653.11,1596.38
  Bottom Layer w10: R108.1@3292.64,1122.8 3292.64,1123.78 3306.34,1137.48 3448.68,1137.48 3536.02,1224.82 3536.02,1299.41 J32.8@3492.64,1342.8
VF2: J32.7 R100.1 U16.6 | length 787.9
  Top Layer w10: J32.7@3492.64,1242.8 3543.27,1293.43 3543.27,1397.8 3672.8,1527.32 U16.6@3672.8,1596.38
  Bottom Layer w10: R100.1@3182.64,1122.8 3236.05,1122.8 3291.16,1177.91 3427.76,1177.91 J32.7@3492.64,1242.8
VIO: C150.1 D301.2 J21.2 J33.4 R40.1 R500.2 R501.2 R502.2 U16.30 | length 3096.1
  Top Layer w10: U16.30@3692.48,1919.21 3691.57,1920.12 3691.57,1981.1 3708.27,1997.8 v1(3708.27,2022.8) ; v1@3708.27,2032.95 C150.1@3708.27,2069.17 ; R502.2@3904.76,2057.8 3929.51,2057.8 3929.51,2060.12 3934.45,2065.06 3965.53,2065.06 v1(3968.27,2067.8) 3971.1,2064.96 4015.44,2064.96 4038.64,2088.17 ; R500.2@3904.76,2267.8 R501.2@3904.76,2197.8 3958.27,2197.8 ; 3958.26,2198.21 4069,2199.07 ; 4040.41,2088.17 4038.64,2088.17 ; R40.1@4086.81,2215.38 4076.43,2205 4069.02,2197.58 4069.02,2158.06 ; D301.2@4098.07,2159.29 4096.84,2158.06 4069.02,2158.06 ; 4038.64,2088.17 4069.02,2118.54 4069.02,2158.06
  Mid-Layer 2 w10: v1(3708.27,2022.8) 3708.27,2026.8 3733.27,2051.8 3733.27,2332.8 3783.27,2382.8 3958.27,2382.8 4263.27,2077.8 4263.27,1783.65 4193.27,1713.66 4164.99,1713.66 4129.64,1678.31 4093.78,1678.31 J33.4@4083.27,1667.8
  Bottom Layer w10: J21.2@3253.27,2337.8 3498.27,2092.8 3622.12,2092.8 3685.74,2029.17 3697.88,2029.17 3704.26,2022.8 v1(3708.27,2022.8) 3708.54,2022.52 3926.82,2022.52 3968.27,2063.97 v1(3968.27,2067.8)
VSUP: C89.1 C90.1 D18.1 R220.2 TP4.1 U16.36 | length 763.8
  Top Layer w12: v1(3403.27,1947.8) 3425.51,1970.04 3425.51,1980.98 3432.32,1987.8 C90.1@3436.26,1987.8 ; R220.2@3437.64,2212.8 3437.64,2206.3 3413.27,2181.93 3413.27,2127.26 3432.64,2107.89 C89.1@3432.64,2042.8 3432.64,2038.8 3434.45,2036.98 3434.45,1989.61 C90.1@3436.26,1987.8 ; U16.36@3574.28,1917.8 3518.27,1917.8 3454.08,1981.98 3442.07,1981.98 C90.1@3436.26,1987.8
  Mid-Layer 2 w10: TP4.1@3113.27,1962.8 TP4.1@3125.44,1950.63 ; v1@3400.44,1950.63 v1(3403.27,1947.8)
  Mid-Layer 2 w12: TP4.1@3125.44,1950.63 v1@3400.44,1950.63
pads on no net: FID1.1 FID2.1 FID3.1 FID4.1 FID5.1 FID6.1 H1.1 H2.1 H3.1 H4.1 H5.0 H6.0 H7.0 H8.0 J22.3 J24.1 J28. J29. J36.2 J36.3 J36.MH1 J36.MH2 J37.2 J37.3 J37.MH1 J37.MH2 LBL1.0 T3.2 T4.2 U1.2 U2.4 U2.5 U2.6 U2.7 U2.8 U3.5 U6.1 U11.4 U11.5 U11.6 U11.7 U11.8 U16.40 U100.2
copper on no net: | length 18.1
  Bottom Layer w10: 1114.26,1712.8 1124.26,1722.8 v1(1128.27,1722.8)

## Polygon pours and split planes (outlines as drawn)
GND on Top Layer "TOP_LAYER_GND_P057" (solid, remove dead copper, pour order 57): 2678.27,3946.63 2678.27,2951.63 2883.27,2951.63 2883.27,1762.8 1013.27,1762.8 1013.27,702.8 1143.27,702.8 1218.27,777.8 1218.27,921.63 1809.43,1512.8 2743.27,1512.8 2743.27,1392.8 3133.27,1002.8 5608.27,1002.8 5608.27,2322.8 4183.27,2322.8 4183.27,3977.8 2678.27,3977.8
GND_ISO on Top Layer "TOP_LAYER_GND_ISO_P059" (solid, remove dead copper, pour order 59): 43.27,4002.8 2143.27,4002.8 2143.27,3007.8 1988.27,3007.8 1973.27,3022.8 1973.27,3122.8 1693.27,3402.8 1178.27,3402.8 1108.27,3472.8 43.27,3472.8
24V_LV on Top Layer "TOP_LAYER_24V_LV_P056" (solid, pour order 56): 809.28,2627.8 958.27,2627.8 983.27,2602.8 1058.27,2602.8 1078.27,2622.8 1143.27,2622.8 1145.77,2625.3 1143.27,2627.8 1143.27,2677.8 1128.27,2692.8 1128.27,2842.8 1068.27,2842.8 1048.27,2842.8 1038.27,2832.8 1038.27,2712.8 1033.27,2707.8 838.27,2707.8 838.27,2722.8 809.28,2751.78
24V_LV on Top Layer "TOP_LAYER_24V_LV_P055" (solid, pour order 55): 1158.27,2942.8 768.27,2942.8 613.27,2787.8 613.27,2657.8 643.27,2627.8 833.27,2627.8 833.27,2737.8 768.27,2802.8 768.27,2832.8 808.27,2872.8 1258.27,2872.8 1263.27,2877.8 1263.27,3037.8 1163.27,3037.8 1158.27,3042.8 1158.27,2982.8
KL30_PROTECT on Top Layer "TOP_LAYER_KL30_PROTECT_P054" (solid, pour order 54): 1575.77,3080.3 1538.27,3042.8 1538.27,2922.8 1458.27,2922.8 1448.27,2912.8 1413.27,2912.8 1383.27,2882.8 1293.27,2882.8 1293.27,3017.8 1428.27,3017.8 1573.27,3157.8
KL30_PROTECT on Top Layer "TOP_LAYER_KL30_PROTECT_P053" (solid, pour order 53): 1628.27,3377.8 1628.27,3332.8 1643.27,3317.8 1643.27,3197.8 1603.27,3157.8 1568.83,3153.51 1563.27,3067.8 1943.27,3067.8 1943.27,3127.8 1693.27,3377.8
KL30_IN on Top Layer "TOP_LAYER_KL30_IN_P052" (solid, pour order 52): 1528.07,3382.3 1617.77,3382.3 1618.27,3382.8 1618.27,3332.8 1603.27,3317.8 1603.27,3197.8 1473.27,3197.8 1473.27,3287.8 1288.27,3287.8 1283.27,3292.8 1303.27,3312.8 1528.07,3312.8 1527.83,3382.36
KL30_IN on Top Layer "TOP_LAYER_KL30_IN_P051" (solid, remove dead copper, pour order 51): 1303.27,3372.8 1303.27,3312.8 1263.27,3272.8 1258.27,3272.8 1258.27,3047.8 1253.27,3052.8 1148.27,3052.8 1148.27,3237.8 873.27,3237.8 873.27,3067.8 768.27,3067.8 763.27,3072.8 763.27,3372.8
GND on Mid-Layer 1 "MID-LAYER_1_GND_P065" (solid, remove dead copper, pour order 65): 2678.27,3977.8 4183.27,3977.8 4183.27,2322.8 5608.27,2322.8 5613.27,2317.8 5613.27,1002.8 4234.59,1002.8 4188.27,956.47 4188.27,767.8 3728.27,767.8 3718.27,757.8 3718.27,697.8 3393.27,697.8 3278.27,812.8 3278.27,887.8 3093.27,887.8 3008.27,802.8 2800.44,802.8 2678.27,924.97 2678.27,972.8 2400.84,972.8 2391.26,982.38 2393.27,984.4 2393.27,1512.8 1808.27,1512.8 1301.62,1006.15 1246.62,1006.15 1198.27,957.8 1198.27,732.8 1168.27,702.8 1013.27,702.8 1013.27,1762.8 2883.27,1762.8 2883.27,2947.8 2878.27,2952.8 2678.27,2952.8
GND_ISO on Mid-Layer 1 "MID-LAYER_1_GND_ISO_P060" (solid, remove dead copper, pour order 60): 45.84,4002.8 40.84,3477.8 1103.27,3477.8 1173.27,3407.8 1693.27,3407.8 1978.27,3122.8 1978.27,3002.8 1983.27,2997.8 2143.27,2997.8 2143.27,4002.8
GND_LV on Mid-Layer 1 "MID-LAYER_1_GND_LV_P058" (solid, remove dead copper, pour order 58): 1123.27,3437.8 1173.27,3387.8 1648.27,3387.8 1953.27,3082.8 1953.27,2952.8 2043.27,2952.8 2043.27,2307.8 43.27,2307.8 43.27,3437.8
GND on Mid-Layer 2 "MID-LAYER_2_GND_P066" (solid, remove dead copper, pour order 66): 2678.27,3977.8 4183.27,3977.8 4183.27,2322.8 5608.27,2322.8 5613.27,2317.8 5613.27,1002.8 4234.59,1002.8 4188.27,956.47 4188.27,767.8 3728.27,767.8 3718.27,757.8 3718.27,697.8 3393.27,697.8 3278.27,812.8 3278.27,887.8 3093.27,887.8 3008.27,802.8 2800.44,802.8 2678.27,924.97 2678.27,972.8 2400.84,972.8 2391.26,982.38 2393.27,984.4 2393.27,1512.8 1808.27,1512.8 1301.62,1006.15 1246.62,1006.15 1198.27,957.8 1198.27,732.8 1173.27,707.8 1013.27,707.8 1013.27,1762.8 2883.27,1762.8 2883.27,2947.8 2878.27,2952.8 2678.27,2952.8
GND_LV on Mid-Layer 2 "MID-LAYER_2_GND_LV_P062" (solid, remove dead copper, pour order 62): 43.27,3427.8 1128.27,3427.8 1168.27,3387.8 1668.27,3387.8 1963.27,3092.8 1963.27,2952.8 2038.27,2952.8 2038.27,2312.8 43.27,2312.8
GND_ISO on Mid-Layer 2 "MID-LAYER_2_GND_ISO_P061" (solid, remove dead copper, pour order 61): 43.27,3997.8 43.27,3477.8 1103.27,3477.8 1178.27,3402.8 1698.27,3402.8 1973.27,3127.8 1973.27,2997.8 2143.27,2997.8 2143.27,4002.8 2138.27,3997.8
GND on Bottom Layer "BOTTOM_LAYER_GND_P067" (solid, remove dead copper, pour order 67): 2679.22,3977.8 4184.22,3977.8 4184.22,2348.47 5609.22,2348.47 5614.22,2343.47 5614.22,1002.8 4209.87,1002.8 4189.22,982.15 4189.22,793.47 3729.22,793.47 3719.22,783.47 3719.22,723.47 3394.22,723.47 3279.22,838.47 3279.22,913.47 3094.22,913.47 3009.22,828.47 2801.39,828.47 2679.22,950.64 2679.22,998.47 2401.8,998.47 2392.21,1008.06 2394.22,1010.07 2394.22,1517.8 1788.54,1517.8 1302.58,1031.83 1247.58,1031.83 1198.27,982.52 1198.27,732.8 1178.27,712.8 1014.22,712.8 1014.22,1762.8 2884.22,1762.8 2884.22,2952.8 2679.22,2952.8
GND_LV on Bottom Layer "BOTTOM_LAYER_GND_LV_P064" (solid, remove dead copper, pour order 64): 43.27,3422.8 1128.27,3422.8 1163.27,3387.8 1683.27,3387.8 1683.27,3377.8 1958.27,3102.8 1958.27,2947.8 2043.27,2947.8 2043.27,2312.8 43.27,2312.8
GND_ISO on Bottom Layer "BOTTOM_LAYER_GND_ISO_P063" (solid, remove dead copper, pour order 63): 43.27,3477.8 1108.27,3477.8 1183.27,3402.8 1698.27,3402.8 1973.27,3127.8 1973.27,2997.8 2143.27,2997.8 2143.27,4002.8 2138.27,3997.8 43.27,3997.8

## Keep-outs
Keep-Out Layer:
  text ".Layer_Name" at -1903.32,-2226.6 h60

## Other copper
Top Layer:
  text ".Layer_Name" at -1903.32,-2226.6 h60
Bottom Layer:
  text ".Layer_Name" at -1903.32,-2226.6 h60

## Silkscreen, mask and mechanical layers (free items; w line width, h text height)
Top Overlay:
  text "AVDD" at 2899.27,2198.8 h30
  text "DVDD" at 2733.38,2073.76 h30
  text "VSUP" at 2883.38,1943.76 h30
  text "TSREF" at 2738.38,1813.76 h30
  text "BATN" at 5084.27,998.8 h30
  text "BATP" at 1504.27,973.8 h30
  text "RACKN" at 2222.27,318.8 h30 r90
  text "RACKN" at 4059.27,303.8 h30
  text ".Layer_Name" at -1903.32,-2226.6 h60
Bottom Overlay:
  text ".Layer_Name" at -1903.32,-2226.6 h60
Top Paste:
  text ".Layer_Name" at -1903.32,-2226.6 h60
Bottom Paste:
  text ".Layer_Name" at -1903.32,-2226.6 h60
Top Solder:
  text ".Layer_Name" at -1903.32,-2226.6 h60
  text ".Layer_Name" at -1903.32,-2226.6 h60
Bottom Solder:
  text ".Layer_Name" at -1903.32,-2226.6 h60
Drill Guide:
  text ".Layer_Name" at -1903.32,-2226.6 h60
M1 Board Outline:
  lines w10: 2.19,3.66 2.19,4035.43 6240.16,4025.59 6250,0 2.19,3.66 ; 3.27,27.8 6228.27,32.8 6228.27,4037.8 3.27,4037.8 3.27,27.8
  text ".Layer_Name" at -1903.32,-2226.6 h60
M2 Board Dimensions:
  text ".Layer_Name" at -1903.32,-2226.6 h60
M3 3D STEP Top:
  text ".Layer_Name" at -1903.32,-2226.6 h60
M4 3D STEP Bottom:
  text ".Layer_Name" at -1903.32,-2226.6 h60
M5 Assembly Top:
  lines w10: -2772.32,-2298.28 3827.68,-2298.28 ; -2772.32,-2094.94 3829.68,-2094.94 ; -2772.32,-1891.61 -2772.32,-2501.61 1232.68,-2501.61 3829.68,-2501.61 3829.68,-1891.61 -2771.82,-1891.61 -2771.82,-2501.61 -1196.32,-2501.61 ; -307.32,-2501.61 -307.32,-1891.61 ; 959.68,-2094.94 959.68,-1891.61 ; 1799.68,-2094.94 1799.68,-1891.61 ; 2421.68,-2508.11 2421.68,-2305.28
  text "PCB VIEWED FROM TOP SIDE" at -2708.82,-2023.78 h60
  text "BOARD #:" at -232.32,-2023.78 h60
  text ".PRJ_Number" at 313.18,-2023.78 h60
  text "REV:" at 1157.68,-2023.78 h60
  text ".PCB_Rev" at 1449.18,-2023.78 h60
  text "SVN REV:" at 1995.68,-2023.78 h60
  text ".VersionControl_RevNumber" at 2501.68,-2023.78 h60
  text "TID #:" at -232.32,-2227.11 h60
  text ".TID" at 313.18,-2227.11 h60
  text "PLOT NAME =" at -2708.82,-2432.45 h60
  text ".plot_File_Name" at -1903.32,-2432.45 h60
  text "GENERATED    :" at -230.32,-2432.45 h60
  text ".Print_Date" at 639.18,-2432.45 h60
  text ".Print_Time" at 1368.18,-2432.45 h60
  text "TEXAS INSTRUMENTS" at 2632.68,-2432.45 h60
M6 Assembly Bottom:
  lines w10: -2772.82,-2095.44 3829.18,-2095.44 ; -2770.82,-2298.78 3829.18,-2298.78 ; -1364.82,-2508.61 -1364.82,-2305.78 ; -742.82,-2095.44 -742.82,-1892.11 ; 97.18,-2095.44 97.18,-1892.11 ; 1364.18,-2502.11 1364.18,-1892.11 ; 2253.18,-2502.11 3828.68,-2502.11 3828.68,-1892.11 -2772.82,-1892.11 -2772.82,-2502.11 -175.82,-2502.11 3829.18,-2502.11 3829.18,-1892.11
  text ".VersionControl_RevNumber" at -1444.82,-2024.28 h60
  text "SVN REV:" at -938.82,-2024.28 h60
  text ".PCB_Rev" at -392.32,-2024.28 h60
  text "REV:" at -100.82,-2024.28 h60
  text ".PRJ_Number" at 743.68,-2024.28 h60
  text "BOARD #:" at 1289.18,-2024.28 h60
  text "PCB VIEWED FROM BOTTOM SIDE" at 3765.68,-2024.28 h60
  text ".TID" at 743.68,-2227.61 h60
  text "TID #:" at 1289.18,-2227.61 h60
  text "TEXAS INSTRUMENTS" at -1575.82,-2432.95 h60
  text ".Print_Time" at -311.32,-2432.95 h60
  text ".Print_Date" at 417.68,-2432.95 h60
  text "GENERATED    :" at 1287.18,-2432.95 h60
  text ".plot_File_Name" at 2960.18,-2432.95 h60
  text "PLOT NAME =" at 3765.68,-2432.95 h60
M9 Title Sheet:
  drawing of 57 lines, arcs and shapes, not listed
  text "1" at -1740.48,6668.39 h70
  text "2" at 755.18,6668.39 h70
  text "3" at 3244.53,6668.39 h70
  text "4" at 5751.2,6668.39 h70
  text "5" at 8250.18,6668.39 h70
  text "6" at 10755.18,6668.39 h70
  text "A" at -2896.82,5525.39 h70
  text "A" at 11903.18,5525.39 h70
  text "B" at -2896.82,3145.39 h70
  text "B" at 11903.18,3145.39 h70
  text "C" at -2896.82,770.39 h70
  text "C" at 11903.18,770.39 h70
  text "PROJECT TITLE:" at 8863.18,-1090.61 h45
  text ".PRJ_Title" at 8913.18,-1223.94 h70
  text "DESIGNED FOR:" at 8863.18,-1391.61 h45
  text ".PRJ_Customer" at 8913.18,-1531.61 h70
  text "D" at -2896.82,-1599.61 h70
  text "D" at 11903.18,-1599.61 h70
  text "FILE NAME:" at 8863.18,-1691.61 h45
  text ".PCB_File_Name_No_Path" at 8913.18,-1811.61 h70
  text "Texas Instruments (TI) and/or its licensors do not warrant the accuracy or completeness of this specification" at 3893.68,-1973.45 h45
  text "ENGINEER:" at 8863.18,-1981.61 h45
  text "LAYOUT BY:" at 10368.18,-1981.61 h45
  text "or any information contained therein. TI and/or its licensors do not warrant that this design will meet" at 3848.7,-2086.11 h45
  text ".PRJ_Engineer" at 8913.18,-2136.6 h70
  text ".PCB_Layout" at 10418.68,-2136.6 h70
  text "the specifications, will be suitable for your application or fit for any particular purpose, or will operate in" at 3848.7,-2198.78 h45
  text ".Layer_Name" at -1903.32,-2226.6 h60
  text "ALTIUM DESIGNER VERSION:" at 10368.18,-2291.61 h45
  text "an implementation. TI and/or its licensors do not warrant that the design is production worthy. You should" at 3848.7,-2311.44 h45
  text "completely validate and test your design implementation to confirm the system functionality for your application." at 3893.68,-2424.11 h45
  text ".print_Scale" at 8913.18,-2424.94 h70
  text ".Application_BuildNumber" at 10418.68,-2424.94 h70
  text "1" at -1740.48,-2631.61 h70
  text "2" at 755.18,-2631.61 h70
  text "3" at 3244.53,-2631.61 h70
  text "4" at 5751.2,-2631.61 h70
  text "5" at 8250.18,-2631.61 h70
  text "6" at 10755.18,-2631.61 h70
M10 Fab Notes:
  drawing of 189 lines, arcs and shapes, not listed
  text "DESIGN INFORMATION" at 9901.7,4988.06 h60
  text "MIN. TRACK WIDTH:" at 9257.14,4855.94 h60
  text "8" at 10353.39,4855.94 h60
  text "MIL" at 10508.14,4855.94 h60
  text "7.874" at 10187.01,4734.25 h60
  text "MIN. CLEARANCE:" at 9257.14,4731.81 h60
  text "MIL" at 10508.14,4731.81 h60
  text "MIN. VIA PAD SIZE:" at 9257.14,4607.69 h60
  text "24" at 10323.4,4607.69 h60
  text "MIL" at 10508.14,4607.69 h60
  text "0.05mm (2MIL)" at 9952.14,4477.79 h60
  text "MINIMUM ANNULAR RING" at 8927.91,4469.56 h60
  text "EXTERNAL" at 10660.14,4469.56 h60
  text "PER" at 9127.91,4359.44 h60
  text "IPC-D-275 CLASS 2 LEVEL C" at 9347.91,4359.43 h60
  text "MIL, HOLES" at 10836.14,4258.96 h60
  text "+/-" at 10443.68,4250.37 h60
  text "+/-" at 11297.68,4250.37 h60
  text "REGISTRATION TOLERANCES:" at 8927.91,4249.31 h60
  text "METAL" at 10127.68,4249.31 h60
  text "5" at 10703.89,4249.31 h60
  text "3" at 11536.89,4249.31 h60
  text "MIL" at 11653.14,4249.31 h60
  text "HOLE SIZE TOLERANCE (UNLESS OTHERWISE SPECIFIED):" at 8927.91,4150.99 h60
  text "+/-" at 11297.68,4148.12 h60
  text "3" at 11536.89,4147.06 h60
  text "MIL" at 11653.14,4147.06 h60
  text "MATERIAL:" at 8853.14,4009.41 h60
  text "FR-4 High Tg" at 9839.59,3880.89 h60
  text "X" at 9695.15,3872.9 h60
  text "FR-4" at 9274.15,3868.38 h60
  text "OTHER" at 10762.14,3868.38 h60
  text "62 MIL (1.6mm) +/-10%" at 9594.25,3725.35 h60
  text "X" at 9474.15,3722.9 h60
  text "THICKNESS:" at 8927.91,3717.13 h60
  text "OTHER" at 10879.14,3717.13 h60
  text "TOLERANCE:" at 8927.91,3578.81 h60
  text "X" at 9776.15,3578.81 h60
  text "ANSI IPC-6012 TYPE 3 CLASS 2" at 9954.16,3578.81 h60
  text "OTHER +/-" at 9954.14,3434.62 h60
  text "BOW & TWIST:" at 8927.91,3289.43 h60
  text "X" at 9776.15,3289.43 h60
  text "ANSI IPC-6012 TYPE 3 CLASS 2" at 9954.16,3289.43 h60
  text "OTHER +/-" at 9954.14,3142.74 h60
  text "DRILLING:" at 8853.14,3012.12 h60
  text "NC_DRILL FILES" at 10614.14,2906.93 h60
  text "REFERENCE:" at 8927.91,2902.99 h60
  text "X" at 9585.15,2902.9 h60
  text "AS SHOWN" at 9763.14,2902.99 h60
  text "X" at 10486.15,2902.99 h60
  text "OTHER" at 10912.14,2760.74 h60
  text "PTH COPPER THICKNESS:" at 8927.59,2757.21 h60
  text "X" at 10066.83,2757.21 h60
  text "20-30 um" at 10194.82,2757.21 h60
  text "BOARD FINISH:" at 8853.14,2609.62 h60
  text "SILKSCREEN:" at 9008.37,2499.49 h60
  text "X" at 9966.15,2499.49 h60
  text "TOP" at 10083.14,2499.49 h60
  text "X" at 10476.15,2499.49 h60
  text "BOTTOM" at 10594.14,2499.49 h60
  text "SILKSCREEN COLOR:" at 9008.37,2344.3 h60
  text "X" at 9965.15,2344.3 h60
  text "WHITE" at 10083.14,2344.3 h60
  text "OTHER" at 10594.14,2344.3 h60
  text "X" at 10096.15,2200.85 h60
  text "GREEN" at 10214.14,2200.85 h60
  text "OTHER" at 10832.14,2200.85 h60
  text "SOLDER RESIST COLOR:" at 9008.37,2193.99 h60
  text "X" at 10096.15,2046.6 h60
  text "MATTE" at 10214.14,2046.6 h60
  text "SEMI-GLOSS" at 10831.68,2045.96 h60
  text "IMMERSION GOLD (ENIG)" at 9914.14,1873.83 h60
  text "ENEPIG" at 11251.68,1866.61 h60
  text "SURFACE FINISH:" at 8853.14,1865.61 h60
  text "X" at 9736.15,1865.61 h60
  text "IMM. TIN/SILVER OR EQUIV" at 9182.68,1728.29 h60
  text "OTHER" at 10614.14,1724.36 h60
  text "ARRAY/PANEL:" at 8853.14,1568.98 h60
  text "CUT AND TRIM PER M1 BOARD OUTLINE" at 9914.15,1560.76 h60
  text "N.C. ROUTE" at 9914.14,1424.79 h60
  text "X" at 10602.15,1424.79 h60
  text "V. SCORE" at 10780.14,1424.79 h60
  text "CERTIFICATION:" at 8853.14,1295.66 h60
  text "MATERIALS AND WORKMANSHIP FOR ALL PCBS" at 9578.14,1295.66 h60
  text "TO MEET OR EXCEED THE REQUIREMENTS OF:" at 9578.14,1201.6 h60
  text "X" at 9215.65,1072.97 h60
  text "ANSI IPC-A-600F CLASS ->" at 9343.65,1072.97 h60
  text "X" at 10991.65,1072.97 h60
  text "2" at 11101.65,1072.97 h60
  text "1" at 10786.65,1071.47 h60
  text "3" at 11455.65,1071.47 h60
  text "X" at 10027.65,925.28 h60
  text "RoHS" at 10155.65,925.28 h60
  text "OTHER" at 10800.05,925.28 h60
  text "PER ORDER" at 11197.11,925.28 h60
  text "ALL BOARDS MUST MEET OR EXCEED UL94-V0 REQUIREMENTS." at 8880.68,771.46 h60
  text "PCB MUST BEAR THE UL94V-0 UL REGISTERED MATERIAL ID NUMBER" at 8880.68,655.39 h60
  text "ADDITIONAL REQUIREMENTS:" at 8853.14,485.97 h60
  text "MICROSECTION:" at 8927.91,378.84 h60
  text "YES" at 9833.65,378.84 h60
  text "REQUIRED" at 10695.14,234.51 h60
  text "BARE BOARD ELEC. TEST:" at 8927.91,231.65 h60
  text "NONE" at 10233.65,231.65 h60
  text "X" at 10577.15,231.65 h60
  text "PER ORDER" at 11287.14,231.65 h60
  text "XX MIL VIAS REQUIRE NON-CONDUCTIVE FILL AND PLANARIZE" at 9096.06,26.71 h59
  text "XX MIL VIAS REQUIRE CONDUCTIVE FILL AND PLANARIZE" at 9104.06,-77.27 h60
  text "OUTER XX MIL TRACES REQUIRE 50 OHM SINGLE-ENDED IMPEDANCE" at 9103.08,-240.65 h58
  text "LAYER 2 & 3 (INNER LAYERS) XX MIL WIDE, XX MIL SPACE / TRACES REQUIRE 100 OHM DIFFERENTIAL IMPEDANCE" at 9095.08,-476.37 h60
  text ".Layer_Name" at -1903.32,-2226.6 h60
M11 Gerber Information:
  lines w10: -2772.32,-2298.28 3827.68,-2298.28 ; -2772.32,-2094.94 3829.68,-2094.94 ; -2772.32,-1891.61 -2772.32,-2501.61 1232.68,-2501.61 3829.68,-2501.61 3829.68,-1891.61 -2771.82,-1891.61 -2771.82,-2501.61 -1196.32,-2501.61 ; -307.32,-2501.61 -307.32,-1891.61 ; 959.68,-2094.94 959.68,-1891.61 ; 1799.68,-2094.94 1799.68,-1891.61 ; 2421.68,-2508.11 2421.68,-2305.28
  text "ALL ARTWORK VIEWED FROM TOP SIDE" at -2708.82,-2023.78 h60
  text "BOARD #:" at -232.32,-2023.78 h60
  text ".PRJ_Number" at 313.18,-2023.78 h60
  text "REV:" at 1157.68,-2023.78 h60
  text ".PCB_Rev" at 1449.18,-2023.78 h60
  text "SVN REV:" at 1995.68,-2023.78 h60
  text ".VersionControl_RevNumber" at 2501.68,-2023.78 h60
  text "LAYER NAME =" at -2708.82,-2226.6 h60
  text "TID #:" at -232.32,-2227.11 h60
  text ".TID" at 313.18,-2227.11 h60
  text "PLOT NAME =" at -2708.82,-2432.45 h60
  text ".plot_File_Name" at -1903.32,-2432.45 h60
  text "GENERATED    :" at -230.32,-2432.45 h60
  text ".Print_Date" at 639.18,-2432.45 h60
  text ".Print_Time" at 1368.18,-2432.45 h60
  text "TEXAS INSTRUMENTS" at 2632.68,-2432.45 h60
M12 Stackup:
  drawing of 295 lines, arcs and shapes, not listed
  text "Layer" at 7341.28,6506.83 h60
  text "Name" at 7751.19,6506.83 h60
  text "Material" at 8680.94,6506.83 h60
  text "Thickness" at 9540.7,6506.83 h60
  text "Constant" at 10190.54,6506.83 h60
  text "Board Layer Stack" at 10760.4,6506.83 h60
  text "Top Overlay" at 7751.19,6386.83 h60
  text "Top Solder" at 7751.19,6266.83 h60
  text "Solder Resist" at 8680.94,6266.83 h60
  text "0.40mil" at 9540.7,6266.83 h60
  text "3.5" at 10190.54,6266.83 h60
  text "1" at 7341.28,6146.83 h60
  text "Top Layer" at 7751.19,6146.83 h60
  text "1.40mil" at 9540.7,6146.83 h60
  text "Dielectric1" at 7751.19,6026.83 h60
  text "FR-4 High Tg" at 8680.94,6026.83 h60
  text "59.20mil" at 9540.7,6026.83 h60
  text "4.8" at 10190.54,6026.83 h60
  text "2" at 7341.28,5906.83 h60
  text "Mid-Layer 1" at 7751.19,5906.83 h60
  text "1.40mil" at 9540.7,5906.83 h60
  text "Dielectric2" at 7751.19,5786.83 h60
  text "FR-4" at 8680.94,5786.83 h60
  text "12.60mil" at 9540.7,5786.83 h60
  text "4.8" at 10190.54,5786.83 h60
  text "3" at 7341.28,5666.83 h60
  text "Mid-Layer 2" at 7751.19,5666.83 h60
  text "1.40mil" at 9540.7,5666.83 h60
  text "Dielectric3" at 7751.19,5546.83 h60
  text "FR-4" at 8680.94,5546.83 h60
  text "12.60mil" at 9540.7,5546.83 h60
  text "4.8" at 10190.54,5546.83 h60
  text "4" at 7341.28,5426.83 h60
  text "Bottom Layer" at 7751.19,5426.83 h60
  text "1.40mil" at 9540.7,5426.83 h60
  text "Bottom Solder" at 7751.19,5306.83 h60
  text "Solder Resist" at 8680.94,5306.83 h60
  text "0.40mil" at 9540.7,5306.83 h60
  text "3.5" at 10190.54,5306.83 h60
  text "Bottom Overlay" at 7751.19,5186.83 h60
  text ".Layer_Name" at -1903.32,-2226.6 h60
M13 Component Bodies Top:
  text ".Layer_Name" at -1903.32,-2226.6 h60
M14 Component Bodies Bottom:
  text ".Layer_Name" at -1903.32,-2226.6 h60
M15 Courtyards Top:
  text ".Layer_Name" at -1903.32,-2226.6 h60
M16 Courtyards Bottom:
  text ".Layer_Name" at -1903.32,-2226.6 h60
Drill Drawing:
  text ".Layer_Name" at -1903.32,-2226.6 h60
M17 Embedded Cavity:
  text ".Layer_Name" at -1903.32,-2226.6 h60
M18 Embedded Assembly:
  text ".Layer_Name" at -1903.32,-2226.6 h60
M19 Embedded Keepout:
  text ".Layer_Name" at -1903.32,-2226.6 h60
